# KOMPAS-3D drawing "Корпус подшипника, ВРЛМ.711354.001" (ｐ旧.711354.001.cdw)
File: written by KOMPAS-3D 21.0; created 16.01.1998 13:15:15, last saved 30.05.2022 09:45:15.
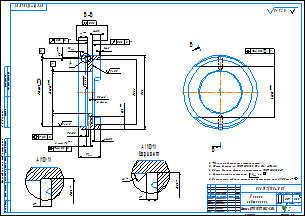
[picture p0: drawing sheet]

Sheet 1: A2, landscape

Document properties: Масса: 0.089348; Знак неуказанной шероховатости: 4; Параметр неуказанной шероховатости: Ra 12,5; Полное имя файла: D:\2023\Чертежи dwg cdw\ВРЛМ.711354.001.cdw

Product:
- Part/product: Корпус подшипника  | designation ВРЛМ.711354.001
    Материал: Сталь 40Х13 ГОСТ 5632-2014 (density 7650 kg/m3)
    Масса: 0.089348
    Полное имя файла: ВРЛМ.711354.001\ВРЛМ.711354.001.m3d

Title block, sheet 1: Наименование: Корпус / подшипника; designation: ВРЛМ.711354.001; Материал: Сталь 40Х13 ГОСТ 5632-2014; Масса: 0,09; Количество листов документа: 1; organisation: ООО "Вириал" / Санкт-Петербург / 2005; Форматы листов документа: A2; stored path: C:\Cadman\Template.sys\template.cdw; file name: 2,5:1; Разработал: Бондаренко; Проверил: Соколик; Т. контр.: Ковеленов; Н. контр.: Кочерга; Утвердил: Соловьев; Разработал, date: 27.05.2022; cell 140: 5; cell 180: 27.05.2022
Table, sheet 1:
  0^Material:VB746596373454C47BCF84398B325B2EF

Views: Вид 1, Спереди, Разрез 2, Выносной элемент 3, Разрез Б-Б, Выносной элемент А, Выносной элемент
Referenced files in W:\ВРЛМ.711354.001\: ВРЛМ.711354.001.m3d
Referenced files in D:\2023\Чертежи dwg cdw\: ВРЛМ.711354.001.m3d
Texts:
  Согласовано: нач. отд. метрологии           Н. Н. Палкина
  Ra 2,5
  вариант
  Ra 12,5
  Ra 12,5 ( )
  ВРЛМ.30421.006.001
  Зам
  ВРЛМ.031-22
  ВРЛМ.711354.001 Корпус подшипника
Dimensions and other numbers on the sheet: 40; 7; 0,5; 17; 2 фаски; 50,5; 58; 53,1; 10,3; 7,5±0,2; 2 отв.; 3; 4,5±0,1; 0,03; 0,05; 1; 6±0,1; 1,5; 33; 2; 53,6; 2,5:1; 2005; 27.05.2022; 0,09; 5

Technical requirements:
  Общие допуски по ГОСТ 30893.1: H14, h14,  IT14/2.
  Общие допуски формы и расположения ГОСТ 30893.2-К.
  Острые кромки притупить  0,2 -0,1 мм.
  Неуказанные радиусы скругления внутренних углов R0,5 max*.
